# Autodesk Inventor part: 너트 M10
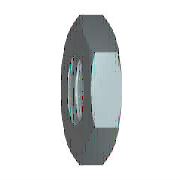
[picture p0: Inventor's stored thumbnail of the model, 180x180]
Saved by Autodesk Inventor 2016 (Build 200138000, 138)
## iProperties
IsCustomPart: 1
Created: 2012-02
Part Number: 너트 M10
Material: 스테인리스강
Description: 미터법 정밀 피치 스레드가 있는 6각 가는 너트(모따기됨)
Document SubType Name: Modeling
Standard: ISO 8675
Designer: mduedu
Standard Revision: Second edition 1999-08-15
Standards Organization: ISO
Language: ko-KR
Size Designation: M10 x 1
Categories: <MemberInstance><Categories><Category DisplayName="조임쇠" InternalName="e4da775c-781d-43d5-af7c-5136215cf5a6" Mnemonic="FSTN"><Category DisplayName="너트" InternalN
Density: 8.08 g/cm^3
Appearance: 기본값
Author: mduedu
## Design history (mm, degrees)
sketch "스케치1"
  geometry: L1 (-9.238, 0)-(-4.619, 8); L2 (-4.619, 8)-(4.619, 8); L3 (4.619, 8)-(9.238, 0); L4 (9.238, 0)-(4.619, -8); L5 (4.619, -8)-(-4.619, -8); L6 (-4.619, -8)-(-9.238, 0); 2 further points
  constraints: 12 end point, 1 coincident, 1 horizontal, 11 other
  dimensions: "d0" = 18.47521 distance of L3.end L1.start (= 1.1547 x SW)
extrude "본체" new body sketch "스케치1" distance "d1" = 5 (= KOH); taper "d2" = 0 deg
sketch "스케치2"
  geometry: L1 (0, 4.619)-(0, 9.238) reference; L2 (0, 9.238)-(5, 9.238) reference; L3 (5, 4.619)-(5, 9.238) reference; L4 (-1, 0)-(6, 0) reference; L5 (1.11, 9.238)-(0, 7.315); L6 (3.89, 9.238)-(5, 7.315)
  constraints: 4 end point, 4 point on line
  dimensions: "d3" = 30 deg angle of L1 L5 (= ANG1); "d4" = 30 deg angle of L3 L6 (= ANG2); "d5" = 14.63 diameter of L5.end L4 (= SW0); "d6" = 14.63 diameter of L6.end L4 (= SW01)
revolve "모따기1" sketch "스케치2" stored, may be unused: angle "d7" = 90 deg
sketch "스케치3"
  geometry: 4 further points
  constraints: 1 coincident, 1 other
hole "스레드" sketch "스케치3" at (0, 0) diameter "d25" = 8.91747; stored, may be unused: countersink angle "d29" = 82 deg, drill point angle "d31" = 118 deg; dims "d26" = 6, "d27" = 4, "d28" = 2, "d30" = 8
workaxis "Work Axis1"
workplane "Work Plane1"
body "Solid1"
chamfer "모따기2" distance "d8" = 0.54127 (= -0.5 x GD1 + 0.5 x NND); stored, may be unused: angle "d9" = 30 deg, second distance "d40" = 0.54127 (= -0.5 x GD1 + 0.5 x NND)
chamfer "모따기3" distance "d10" = 0.54127 (= -0.5 x GD1 + 0.5 x NND); stored, may be unused: angle "d11" = 30 deg, second distance "d41" = 0.54127 (= -0.5 x GD1 + 0.5 x NND)
other parameters: "ANG1" = 30 deg [user parameter; used in 1 equation term], "ANG2" = 30 deg [user parameter; used in 1 equation term], "KOH" = 5 [user parameter; used in 1 equation term], "SW" = 16 [user parameter; used in 1 equation term], "SW0" = 14.63 [user parameter; used in 2 equation terms], "SW01" = 14.63 (= SW0) [user parameter; used in 1 equation term], "GD1" = 8.91747 (computed from THREADDIA, PTC, TOA) [user parameter; used in 4 equation terms], "d13" = 0, "d14" = 0, "d39" = 0, "d42" = 0, "GUL" = 0.54127 (= 0.541266 x PTC) [user parameter], "TOA" = 30 deg [user parameter; used in 1 equation term], "PTC" = 1 [user parameter; used in 4 equation terms], "E0" = 17.77 [user parameter], "GAL" = 0.54127 (= 0.541266 x PTC) [user parameter]
